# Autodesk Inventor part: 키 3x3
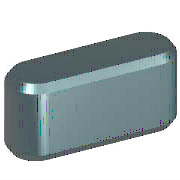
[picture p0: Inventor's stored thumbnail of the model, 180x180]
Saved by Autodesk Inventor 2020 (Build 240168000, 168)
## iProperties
Created: 2012-02
Part Number: 키 3x3
Material: 강철, 연강
Description: 키 및 해당 키홈
Document SubType Name: Modeling
Standard: KS B 1311
Designer: mduedu
Standards Organization: KS
Language: ko-KR
Size Designation: 3 x 3 x 12
Categories: <MemberInstance><Categories><Category DisplayName="샤프트 부품" InternalName="7f7aeb1f-a693-4053-b835-cee3144e0d98" Mnemonic="SHFT"><Category DisplayName="키" Interna
Density: 1 g/cm^3
Appearance: 노란색
IsCustomPart: 1
Author: mduedu
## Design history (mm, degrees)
workplane "Work Plane1"
workplane "Work Plane2"
sketch "스케치1"
  geometry: L1 (1.5, 1.5)-(10.5, 1.5); L2 (10.5, -1.5)-(1.5, -1.5); L3 (0, 9.4)-(0, -7.4) reference; L4 (-5, 0)-(30, 0) reference; L5 (12, 0)-(12, 7); A1 r 1.5 centre (1.5, 0) between (1.5, 1.5) and (1.5, -1.5); A2 r 1.5 centre (10.5, 0) between (10.5, -1.5) and (10.5, 1.5)
  constraints: 6 end point, 5 point on circle, 4 tangent, 3 point on line, 2 centre point, 1 horizontal, 1 parallel, 1 perpendicular
  dimensions: "d0" = 1.5 radius of A1 (= 0.5 x PB); "d13" = 1.5 radius of A2 (= 0.5 x PB); "d14" = 12 distance between parallel lines of L5 L3 (= NLG)
extrude "본체1" new body sketch "스케치1" taper "d3" = 0 deg; stored distance "d4" = 10
workplane "Work Plane3"
body "Solid1"
chamfer "모따기1" distance "d8" = 0.25 (= PHH); stored, may be unused: second distance "d9" = 0.25 (= PHH), angle "d15" = 45 deg
other parameters: "d1" = -1.8 (= -PNT), "d2" = 1.2 (= PH - PNT), "NLG" = 12 [user parameter; used in 3 equation terms], "PB" = 3 [user parameter; used in 2 equation terms], "PNT" = 1.8 [user parameter; used in 2 equation terms], "PH" = 3 [user parameter; used in 1 equation term], "PHH" = 0.25 [user parameter; used in 2 equation terms], "d10" = 0, "d16" = 0, "d17" = 0, "d18" = 0, "WDMIN" = 8 [user parameter], "PLB2" = 12 (= NLG) [user parameter], "PLB1" = 12 (= NLG) [user parameter], "RR" = 0.08 [user parameter], "PUEB" = 1.4 [user parameter]
